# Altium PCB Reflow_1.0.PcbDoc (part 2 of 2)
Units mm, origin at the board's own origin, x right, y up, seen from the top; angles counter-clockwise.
Board outline 183 x 128.5 mm, 2 copper layers (Top Layer, Bottom Layer); 137 components, 94 nets, 418 pads, 91 vias.
Unrouted connection lines stored in the file: 2.
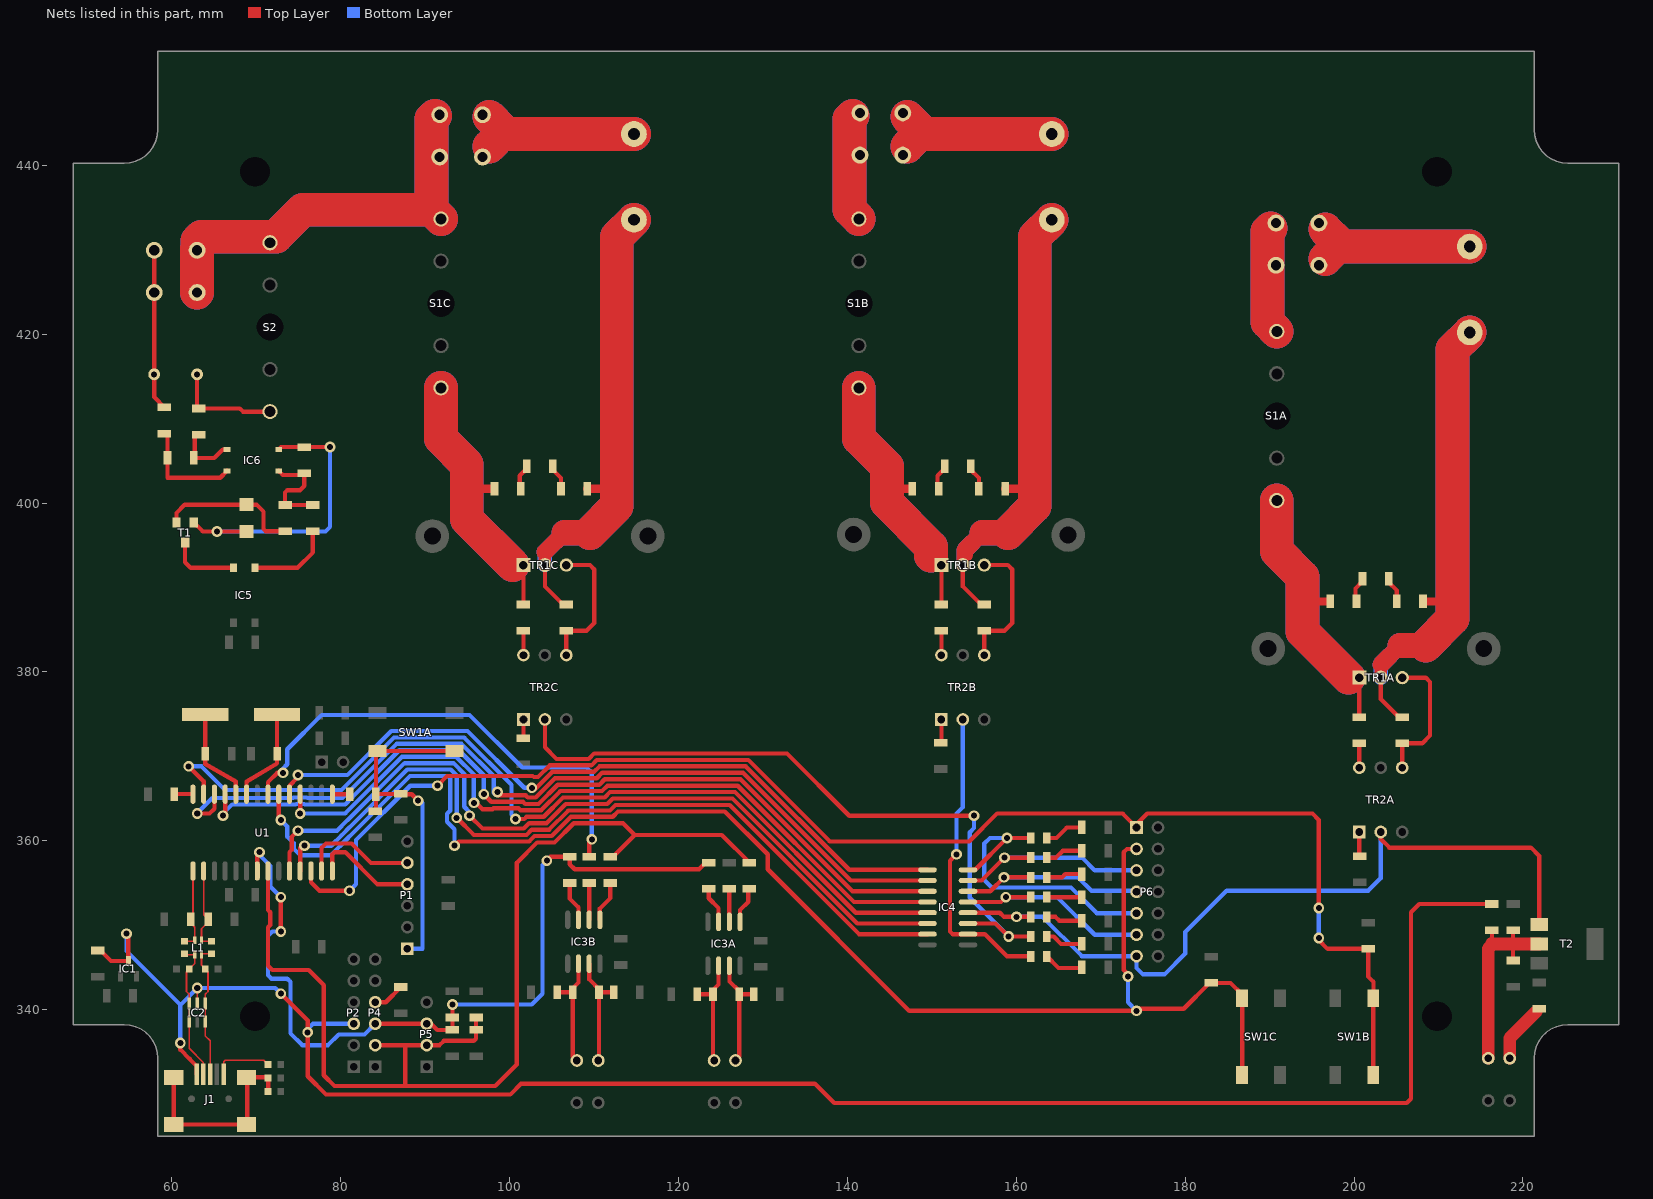
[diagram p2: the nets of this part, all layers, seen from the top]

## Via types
v1: diameter 1.27, hole 0.711, Top Layer to Bottom Layer, 91 vias

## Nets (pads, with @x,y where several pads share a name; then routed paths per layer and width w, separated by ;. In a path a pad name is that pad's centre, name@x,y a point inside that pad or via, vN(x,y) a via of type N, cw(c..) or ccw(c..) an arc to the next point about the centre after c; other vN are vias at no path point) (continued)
L1: K1.1 K4.1 K6.1 K7.1 S1A.1 S1B.1 S1C.1 S2.1 | length 147.7
  Top Layer w0.508: S2.1@71.12,431.292 71.143,431.292 S2.1@71.397,431.546
  Top Layer w4: K1.1@62.973,424.93 K1.1@62.973,429.93 62.992,431.038 63.5,431.546 S2.1@71.12,431.546 ; S2.1@71.397,431.546 72.329,431.546 75.529,434.746 90.745,434.746 ; K4.1@91.136,445.867 90.745,445.476 90.745,434.746 ; S1C.1@91.851,433.64 90.745,434.746 ; K6.1@140.636,445.867 140.245,445.476 140.245,434.746 S1B.1@141.351,433.64 ; K7.1@190.136,432.534 189.745,432.143 189.745,421.413 S1A.1@190.851,420.307
  Bottom Layer w4: K1.1@62.973,424.93 K1.1@62.973,429.93 62.992,431.038 63.5,431.546 S2.1@71.12,431.546 ; S2.1@71.397,431.546 72.329,431.546 75.529,434.746 90.745,434.746 ; K4.1@91.136,445.867 90.745,445.476 90.745,434.746 ; S1C.1@91.851,433.64 90.745,434.746 ; K6.1@140.636,445.867 140.245,445.476 140.245,434.746 S1B.1@141.351,433.64 ; K7.1@190.136,432.534 189.745,432.143 189.745,421.413 S1A.1@190.851,420.307
L_SICHER: C4.1 R33.1 S2.4 | length 12.7
  Top Layer w0.508: C4.1@62.973,415.238 62.973,411.402 R33.1@63.175,411.2 68.027,411.2 68.401,410.826 S2.4@71.609,410.826
MCLR: P1.1 R13.1 R14.2 R15A.1 SW1A.1 SW1A.2 | length 41.5
  Top Layer w0.5: R15A.1@84.074,363.5 84.156,363.582 R14.2@84.156,365.528 ; v1(89.154,364.744) 88.392,365.506 87.178,365.506 R13.1@87.106,365.578 87.056,365.528 R14.2@84.156,365.528 ; SW1A.2@93.45,370.622 SW1A.1@84.35,370.622 84.156,370.428 R14.2@84.156,365.528
  Bottom Layer w0.5: P1.1@87.884,347.218 89.662,347.218 89.662,364.49 v1@89.154,364.998
N: C4.2 K3.1 R35.1 | length 19.1
  Top Layer w0.508: K3.1@57.893,429.93 K3.1@57.893,424.93 C4.2@57.893,415.238 57.893,412.545 R35.1@59.111,411.327
Net*1A_0: *1A.0 R4A.2 R5A.2 TR1A.2 | length 113.1
  Top Layer w0.508: TR1A.2@203.17,379.319 203.17,376.779 205.303,374.646 R5A.2@205.71,374.646
  Top Layer w1: R4A.2@208.175,388.336 211.679,388.336
  Top Layer w1.5: TR1A.2@203.17,379.319 203.17,380.843
  Top Layer w2: 203.17,380.843 205.456,383.129
  Top Layer w3: 205.456,383.129 208.504,383.129
  Top Layer w4: 208.504,383.129 211.679,386.304 211.679,388.336 211.679,418.181 *1A.0@213.711,420.213
  Bottom Layer w1.5: TR1A.2@203.17,379.319 203.17,380.843
  Bottom Layer w1.7: TR1A.2@203.17,379.319 203.17,380.843 TR1A.2@203.17,379.319
  Bottom Layer w2: 203.17,380.843 205.456,383.129 ; 203.17,380.843 205.456,383.129 ; 203.17,380.843 205.456,383.129
  Bottom Layer w3: 205.456,383.129 208.504,383.129
  Bottom Layer w4: 208.504,383.129 211.679,386.304 211.679,388.336 211.679,418.181 *1A.0@213.711,420.213
Net*1A_1: *1A.1 K8.1 | length 40.8
  Top Layer w4: 196.583,428.901 198.055,430.373 ; 196.583,432.417 198.055,430.945 198.055,430.373 ; *1A.1@213.711,430.373 198.055,430.373
  Bottom Layer w4: 196.583,428.901 198.055,430.373 ; 196.583,432.417 198.055,430.945 198.055,430.373 ; *1A.1@213.711,430.373 198.055,430.373
Net*1B_0: *1B.0 R4B.2 R5B.2 TR1B.2 | length 103.6
  Top Layer w0.508: TR1B.2@153.67,392.652 153.67,390.112 155.803,387.979 R5B.2@156.21,387.979
  Top Layer w1: R4B.2@158.675,401.669 162.179,401.669
  Top Layer w1.5: TR1B.2@153.67,392.652 153.67,393.675 153.899,393.903
  Top Layer w2: 153.899,393.903 153.899,394.405 155.956,396.462
  Top Layer w3: 155.956,396.462 159.004,396.462
  Top Layer w4: 159.004,396.462 162.179,399.637 162.179,401.669 162.179,431.514 *1B.0@164.211,433.546
  Bottom Layer w1.5: TR1B.2@153.67,392.652 153.67,393.878 153.899,394.106
  Bottom Layer w2: 153.899,394.106 153.899,394.405 155.956,396.462
  Bottom Layer w3: 155.956,396.462 159.004,396.462
  Bottom Layer w4: 159.004,396.462 162.179,399.637 162.179,431.514 *1B.0@164.211,433.546
Net*1B_1: *1B.1 K2.1 | length 40.8
  Top Layer w4: 147.083,442.234 148.555,443.706 ; K2.1@147.083,445.75 148.555,444.278 148.555,443.706 ; *1B.1@164.211,443.706 148.555,443.706
  Bottom Layer w4: 147.083,442.234 148.555,443.706 ; K2.1@147.083,445.75 148.555,444.278 148.555,443.706 ; *1B.1@164.211,443.706 148.555,443.706
Net*1C_0: *1C.0 R4C.2 R5C.2 TR1C.2 | length 113.1
  Top Layer w0.508: TR1C.2@104.17,392.652 104.17,390.112 106.303,387.979 R5C.2@106.71,387.979
  Top Layer w1: R4C.2@109.175,401.669 112.679,401.669
  Top Layer w1.5: TR1C.2@104.17,392.652 104.17,394.176
  Top Layer w2: 104.17,394.176 106.456,396.462
  Top Layer w3: 106.456,396.462 109.504,396.462
  Top Layer w4: 109.504,396.462 112.679,399.637 112.679,401.669 112.679,431.514 *1C.0@114.711,433.546
  Bottom Layer w1.5: TR1C.2@104.17,392.652 104.17,394.176
  Bottom Layer w1.7: TR1C.2@104.17,392.652 104.17,394.176 TR1C.2@104.17,392.652
  Bottom Layer w2: 104.17,394.176 106.456,396.462 ; 104.17,394.176 106.456,396.462 ; 104.17,394.176 106.456,396.462
  Bottom Layer w3: 106.456,396.462 109.504,396.462
  Bottom Layer w4: 109.504,396.462 112.679,399.637 112.679,401.669 112.679,431.514 *1C.0@114.711,433.546
Net*1C_1: *1C.1 K5.1 | length 40.8
  Top Layer w4: 97.583,442.234 99.055,443.706 ; K5.1@97.583,445.75 99.055,444.278 99.055,443.706 ; *1C.1@114.711,443.706 99.055,443.706
  Bottom Layer w4: 97.583,442.234 99.055,443.706 ; K5.1@97.583,445.75 99.055,444.278 99.055,443.706 ; *1C.1@114.711,443.706 99.055,443.706
NetC3A_1: C3A.1 R3A.2 | length 3
  Top Layer w0.508: R3A.2@200.174,388.336 200.174,389.886 201.011,390.723 C3A.1@201.011,391.003
NetC3A_2: C3A.2 R4A.1 | length 3.1
  Top Layer w0.508: C3A.2@204.111,391.003 204.111,390.596 205.075,389.632 R4A.1@205.075,388.336
NetC3B_1: C3B.1 R3B.2 | length 3
  Top Layer w0.508: R3B.2@150.674,401.669 150.674,403.219 151.511,404.056 C3B.1@151.511,404.336
NetC3B_2: C3B.2 R4B.1 | length 3.1
  Top Layer w0.508: C3B.2@154.611,404.336 154.611,403.929 155.575,402.965 R4B.1@155.575,401.669
NetC3C_1: C3C.1 R3C.2 | length 3
  Top Layer w0.508: R3C.2@101.174,401.669 101.174,403.219 102.011,404.056 C3C.1@102.011,404.336
NetC3C_2: C3C.2 R4C.1 | length 3.1
  Top Layer w0.508: C3C.2@105.111,404.336 105.111,403.929 106.075,402.965 R4C.1@106.075,401.669
NetC7_1: C7.1 FER1.2 J1.6 J1.7 J1.8 J1.9 | length 24
  Top Layer w0.508: J1.8@60.198,331.978 J1.9@60.198,326.39 J1.6@68.834,326.39 68.917,326.473 J1.7@68.917,331.978 ; J1.7@68.834,331.978 J1.7@68.917,331.978 ; FER1.2@71.386,330.295 C7.1@71.386,331.895 71.303,331.978 J1.7@68.917,331.978
NetC9A_1: C9A.1 IC3A.3 K12.1 R12A.2 | length 13.6
  Top Layer w0.508: IC3A.3@126.011,345.199 126.037,345.173 126.037,343.328 127.18,342.185 C9A.1@127.18,341.83 ; K12.1@126.746,333.97 127.18,334.404 C9A.1@127.18,341.83 ; R12A.2@128.906,341.83 C9A.1@127.18,341.83
NetC9A_2: C9A.2 IC3A.2 K11.1 R11A.2 | length 13.4
  Top Layer w0.508: R11A.2@122.227,341.83 C9A.2@124.08,341.83 ; K11.1@124.206,333.97 124.08,334.096 C9A.2@124.08,341.83 ; IC3A.2@124.741,345.199 124.741,342.973 124.08,342.312 C9A.2@124.08,341.83
NetC9B_1: C9B.1 IC3B.3 K10.1 R12B.2 | length 13.7
  Top Layer w0.508: IC3B.3@109.411,345.434 109.437,345.408 109.437,343.563 110.58,342.42 C9B.1@110.58,342.065 ; K10.1@110.49,333.97 110.58,334.06 C9B.1@110.58,342.065 ; R12B.2@112.306,342.065 C9B.1@110.58,342.065
NetC9B_2: C9B.2 IC3B.2 K9.1 R11B.2 | length 13.8
  Top Layer w0.508: R11B.2@105.627,342.065 C9B.2@107.48,342.065 ; K9.1@107.95,333.97 107.48,334.44 C9B.2@107.48,342.065 ; IC3B.2@108.141,345.434 108.141,343.208 107.48,342.547 C9B.2@107.48,342.065
NetC10_1: C10.1 U1.14 | length 2.2
  Top Layer w0.508: C10.1@60.256,365.528 U1.14@62.484,365.515
NetC14_1: C14.1 IC6.1 R32.2 R34.2 | length 12.2
  Top Layer w0.508: IC6.1@72.632,403.808 73.133,403.307 75.452,403.307 R34.2@75.673,403.528 75.673,402.03 75.165,401.522 73.667,401.522 73.387,401.242 C14.1@73.387,399.77 ; C14.1@73.413,399.77 R32.2@76.689,399.77
NetC14_2: C14.2 D1.A T1.E | length 16.9
  Top Layer w0.508: T1.E@60.534,397.712 60.534,398.829 61.512,399.808 D1.A@68.815,399.808 70.021,399.808 70.847,398.982 70.847,396.924 71.101,396.67 C14.2@73.387,396.67
NetC15_1: C15.1 IC6.3 R33.2 | length 7
  Top Layer w0.508: C15.1@62.566,405.332 65.005,405.332 66.021,406.348 IC6.3@66.522,406.348 ; C15.1@62.695,405.461 R33.2@62.695,408.131
NetC15_2: C15.2 IC6.4 R35.2 | length 12.8
  Top Layer w0.508: R35.2@59.111,408.227 59.466,407.872 C15.2@59.466,405.332 59.466,402.997 65.711,402.997 IC6.4@66.522,403.808
NetD1_K: D1.K IC6.2 R34.1 T1.B | length 36
  Top Layer w0.508: T1.B@62.566,397.712 63.657,396.621 65.311,396.621 v1(65.322,396.633) D1.K@68.815,396.633 ; IC6.2@72.632,406.348 72.912,406.628 R34.1@75.673,406.628 v1(78.721,406.628)
  Bottom Layer w0.508: v1(65.322,396.633) 78.175,396.633 78.721,397.178 v1(78.721,406.628)
NetFER2_1: FER2.1 J1.1 | length 7
  Top Layer w0.2: J1.1@66.117,332.338 66.117,333.833 66.294,334.01 70.878,334.01 FER2.1@71.386,333.502
NetIC3A_5: IC3A.5 R29.2 | length 4.4
  Top Layer w0.508: IC3A.5@127.281,350.399 127.281,351.79 128.27,352.779 128.27,354.175 R29.2@128.399,354.304
NetIC3A_6: IC3A.6 R28.2 | length 3.9
  Top Layer w0.508: IC3A.6@126.011,350.399 R28.2@126.011,354.304
NetIC3A_7: IC3A.7 R30.2 | length 4.4
  Top Layer w0.508: R30.2@123.573,354.304 123.573,353.185 124.741,352.017 IC3A.7@124.741,350.399
NetIC3B_5: IC3B.5 R24.2 | length 4.9
  Top Layer w0.508: IC3B.5@110.681,350.634 110.681,351.981 111.925,353.225 R24.2@111.925,354.993
NetIC3B_6: IC3B.6 R23.2 | length 4.4
  Top Layer w0.508: IC3B.6@109.411,350.634 109.411,354.967 R23.2@109.437,354.993
NetIC3B_7: IC3B.7 R25.2 | length 4.8
  Top Layer w0.508: R25.2@107.099,354.993 107.099,353.149 108.141,352.107 IC3B.7@108.141,350.634
NetIC4_1: IC4.1 U1.5 | length 88.5
  Top Layer w0.508: U1.5@73.914,365.515 73.914,366.522 74.93,367.538 v1(74.93,367.792) ; v1(102.616,366.268) 102.87,366.014 102.901,366.014 105.052,368.165 109.985,368.165 110.628,368.808 127.954,368.808 140.207,356.555 IC4.1@149.48,356.555
  Bottom Layer w0.508: v1(74.93,367.792) 80.772,367.792 85.979,372.999 95,372.999 101.731,366.268 v1(102.616,366.268)
NetIC4_2: IC4.2 U1.12 | length 105.1
  Top Layer w0.508: v1(62.992,363.22) 64.454,363.22 65.024,363.79 U1.12@65.024,365.515 ; v1(98.552,365.76) 98.298,365.76 98.679,365.379 101.889,365.379 102.143,365.125 103.089,365.125 105.368,367.403 110.301,367.403 110.944,368.046 127.639,368.046 140.4,355.285 IC4.2@149.48,355.285
  Bottom Layer w0.508: v1(62.992,363.22) 62.992,363.282 64.774,365.063 74.333,365.063 74.395,365.125 75.973,365.125 76.035,365.063 80.199,365.063 81.149,366.014 86.61,371.475 94.288,371.475 98.109,367.654 98.109,365.695 98.298,365.506 98.298,365.76 v1(98.552,365.76)
NetIC4_3: IC4.3 U1.11 | length 100.5
  Top Layer w0.508: v1@65.786,362.712 66.294,363.22 U1.11@66.294,365.515 ; v1(96.936,365.506) 97.825,364.617 101.573,364.617 101.827,364.363 103.405,364.363 105.683,366.641 110.617,366.641 111.259,367.284 127.323,367.284 140.592,354.015 IC4.3@149.48,354.015
  Bottom Layer w0.508: v1(66.04,362.966) 66.04,363.22 67.121,364.301 74.649,364.301 74.711,364.363 75.657,364.363 75.719,364.301 80.514,364.301 81.338,365.125 86.926,370.713 93.973,370.713 96.936,367.75 v1(96.936,365.506)
NetIC4_4: IC4.4 U1.4 | length 91
  Top Layer w0.508: v1(75.184,363.22) U1.4@75.184,365.515 ; v1(95.758,364.49) 96.012,364.49 96.774,363.728 97.952,363.728 98.079,363.855 101.034,363.855 101.288,363.601 103.721,363.601 105.999,365.879 110.932,365.879 111.575,366.522 127.007,366.522 140.784,352.745 IC4.4@149.48,352.745
  Bottom Layer w0.508: v1(75.184,363.22) 80.511,363.22 87.242,369.951 93.657,369.951 95.758,367.85 v1(95.758,364.49)
NetIC4_5: IC4.5 U1.13 | length 108.6
  Top Layer w0.508: v1(61.976,368.808) 63.754,367.03 U1.13@63.754,365.515 ; v1(100.688,362.585) 101.734,362.585 101.988,362.839 104.036,362.839 106.314,365.117 111.248,365.117 111.891,365.76 126.692,365.76 140.977,351.475 IC4.5@149.48,351.475
  Bottom Layer w0.508: v1(61.976,368.808) 63.5,368.808 66.294,366.014 80.072,366.014 86.295,372.237 94.604,372.237 100.203,366.638 100.203,363.07 v1(100.688,362.585)
NetIC4_6: IC4.6 U1.24 | length 96.6
  Top Layer w0.508: U1.24@73.914,356.415 73.914,358.648 74.168,358.902 74.168,360.426 v1(74.93,361.188) ; v1@95.25,363.22 v1(95.25,362.966) 96.774,361.442 101.669,361.442 102.304,362.077 104.352,362.077 106.63,364.355 111.563,364.355 112.206,364.998 126.376,364.998 141.169,350.205 IC4.6@149.48,350.205
  Bottom Layer w0.508: v1(74.93,361.188) 79.544,361.188 80.746,362.39 80.758,362.39 87.557,369.189 93.341,369.189 94.615,367.915 94.615,364.017 95.25,363.382 v1(95.25,362.966)
NetIC4_7: IC4.7 U1.25 | length 95.2
  Top Layer w0.508: U1.25@75.184,356.415 75.184,359.156 75.438,359.41 v1(75.692,359.41) ; v1(93.726,362.712) 95.758,360.68 101.985,360.68 102.62,361.315 104.668,361.315 106.946,363.593 111.879,363.593 112.522,364.236 126.061,364.236 141.362,348.935 IC4.7@149.48,348.935
  Bottom Layer w0.508: v1(75.692,359.41) 78.856,359.41 80.123,360.678 80.123,360.69 81.062,361.628 81.074,361.628 87.873,368.427 93.026,368.427 93.726,367.727 v1(93.726,362.712) v1@93.98,362.966
NetIC5_A: IC5.A R32.1 | length 10.1
  Top Layer w0.508: IC5.A@69.831,392.326 74.859,392.326 76.689,394.156 R32.1@76.689,396.67
NetIC5_KA: IC5.KA T1.C | length 8.3
  Top Layer w0.508: T1.C@61.55,395.299 61.55,392.987 62.211,392.326 IC5.KA@67.291,392.326
NetK13_1: K13.1 R36.2 R37.2 R38.2 T2.2 | length 24.6
  Top Layer w0.508: 216.342,347.66 R36.2@216.342,349.412 ; R38.2@218.842,345.812 218.842,347.776 R37.2@218.842,349.412
  Top Layer w1.5: K13.1@215.9,334.224 215.9,347.218 216.342,347.66 ; 216.342,347.876 216.442,347.776 218.842,347.776 T2.2@221.942,347.776
NetK14_1: K14.1 R39.1 | length 6.8
  Top Layer w1.5: K14.1@218.44,334.224 218.44,336.61 R39.1@221.585,339.755
NetOPTO1A_A: OPTO1A.A R10A.1 | length 4.8
  Top Layer w0.508: OPTO1A.A@163.614,346.31 164.992,344.932 167.687,344.932 R10A.1@167.772,345.017
NetOPTO1B_A: OPTO1B.A R10B.1 | length 4.5
  Top Layer w0.508: OPTO1B.A@163.614,348.647 164.433,348.647 165.304,347.776 R10B.1@167.772,347.776
NetOPTO1C_A: OPTO1C.A R10C.1 | length 4.3
  Top Layer w0.508: OPTO1C.A@163.614,350.985 164.635,350.985 165.086,350.534 R10C.1@167.772,350.534
NetOPTO1D_A: OPTO1D.A R10D.1 | length 4.2
  Top Layer w0.508: OPTO1D.A@163.614,353.322 167.743,353.322 R10D.1@167.772,353.293
NetOPTO1E_A: OPTO1E.A R10E.1 | length 4.7
  Top Layer w0.508: OPTO1E.A@163.614,360.334 164.754,360.334 165.989,361.569 R10E.1@167.772,361.569
NetOPTO1F_A: OPTO1F.A R10F.1 | length 4.3
  Top Layer w0.508: OPTO1F.A@163.614,355.659 165.413,355.659 165.806,356.052 R10F.1@167.772,356.052
NetOPTO1G_A: OPTO1G.A R10G.1 | length 4.5
  Top Layer w0.508: OPTO1G.A@163.614,357.997 164.703,357.997 165.516,358.81 R10G.1@167.772,358.81
NetP4_2: P4.2 P5.2 R21.2 R24.1 R27.1 R29.1 U1.22 | length 133.3
  Top Layer w0.508: U1.22@71.374,356.415 71.374,351.79 71.628,351.536 71.628,350.012 71.374,349.758 71.374,345.186 71.882,344.678 76.2,344.678 77.978,342.9 77.978,332.232 79.248,330.962 87.63,330.962 ; P4.2@84.074,335.788 87.63,335.788 ; R27.1@96.012,339.064 R21.2@96.012,337.592 96.012,336.55 95.758,336.296 92.202,336.296 91.694,335.788 P5.2@90.17,335.788 87.63,335.788 ; R24.1@111.553,358.093 112.221,358.093 114.808,360.68 ; R29.1@128.399,357.404 125.123,360.68 114.808,360.68 ; 87.63,330.962 87.63,335.788 ; 87.63,330.962 98.298,330.962 100.838,333.502 100.838,357.378 103.251,359.791 105.299,359.791 107.577,362.069 113.419,362.069 114.808,360.68
NetP4_3: P4.3 P5.3 R22.2 R25.1 R26.1 R30.1 U1.21 | length 101
  Top Layer w0.508: U1.21@70.104,356.415 70.104,358.394 v1(70.358,358.648) ; v1(72.898,349.25) v1(72.898,353.314) ; P4.3@84.074,338.328 P5.3@90.17,338.328 90.678,338.328 91.414,337.592 R22.2@93.218,337.592 R26.1@93.218,339.064 v1(93.218,340.614) ; v1(104.394,357.632) 104.394,357.65 104.837,358.093 R25.1@107.099,358.093 107.099,357.213 107.696,356.616 122.428,356.616 123.216,357.404 R30.1@123.573,357.404
  Bottom Layer w0.508: v1@69.977,358.648 v1@70.019,358.648 ; v1@69.977,358.649 70.018,358.649 v1@70.019,358.648 ; v1(70.358,358.648) v1@70.019,358.648 ; v1(72.898,349.25) 71.882,349.25 71.374,348.742 71.374,344.083 71.795,343.662 73.66,343.662 74.041,343.281 74.041,337.185 75.438,335.788 78.486,335.788 79.756,337.058 82.804,337.058 P4.3@84.074,338.328 ; v1(72.898,353.314) 71.67,354.542 71.67,356.997 v1@70.019,358.648 ; v1(93.218,340.614) 102.616,340.614 103.886,341.884 103.886,357.124 v1(104.394,357.632)
NetP4_4: P4.4 R20.1 | length 3.8
  Top Layer w0.508: P4.4@84.074,340.868 85.318,340.868 R20.1@87.122,342.672
NetP6_1: P6.1 R15B.1 SW1B.1 SW1B.2 U1.26 | length 174.8
  Top Layer w0.508: U1.26@76.454,356.415 76.454,355.092 77.47,354.076 v1(81.026,354.076) ; v1(91.44,366.522) 92.583,367.665 102.706,367.665 ; 102.87,367.538 103.347,367.538 104.736,368.927 109.67,368.927 110.313,369.57 128.27,369.57 137.922,359.918 154.432,359.918 157.734,363.22 172.593,363.22 P6.1@174.244,361.569 174.244,361.95 175.514,363.22 195.072,363.22 195.834,362.458 195.834,356.616 ; v1(195.834,348.488) 195.834,348.234 196.876,347.192 R15B.1@201.676,347.192 201.676,343.916 202.311,343.281 SW1B.2@202.311,341.071 ; v1(195.834,352.044) 195.834,356.616 ; 195.834,355.854 195.834,356.616 ; SW1B.1@202.275,332.254 SW1B.2@202.275,341.354 SW1B.2@202.275,341.666
  Bottom Layer w0.508: v1(81.026,354.076) 81.788,354.838 81.788,360.089 88.221,366.522 v1(91.44,366.522) ; v1(195.834,348.488) v1(195.834,352.044)
NetP6_2: P6.2 R15C.1 SW1C.1 SW1C.2 U1.6 | length 176.5
  Top Layer w0.508: U1.6@72.644,365.515 72.644,362.712 v1(72.898,362.458) ; v1(93.472,359.41) 93.98,359.918 102.3,359.918 102.935,360.553 104.983,360.553 107.261,362.831 107.893,362.831 112.195,362.831 112.838,363.474 125.476,363.474 130.556,358.394 130.556,356.616 147.32,339.852 v1(174.244,339.852) 174.498,340.106 179.832,340.106 182.886,343.16 R15C.1@183.092,343.16 185.363,343.16 SW1C.1@186.715,341.808 ; v1(173.228,343.916) 173.228,344.17 172.72,344.678 172.72,358.648 173.101,359.029 P6.2@174.244,359.029 ; SW1C.2@186.766,332.378 SW1C.1@186.766,341.478
  Bottom Layer w0.508: v1(72.898,362.458) 73.66,361.696 73.66,360.488 74.407,359.741 74.407,359.079 75.219,358.267 78.79,358.267 80.885,360.362 80.885,360.374 81.377,360.866 81.389,360.866 88.188,367.665 92.71,367.665 92.964,367.411 92.964,363.566 92.583,363.185 92.583,362.239 93.472,361.35 v1(93.472,359.41) ; v1(173.228,343.916) 173.228,340.868 v1(174.244,339.852)
NetR1A_2: R1A.2 TR2A.1 | length 2.9
  Top Layer w0.508: TR2A.1@200.63,361.031 200.63,358.196 R1A.2@200.66,358.166
NetR1B_2: R1B.2 TR2B.1 | length 2.8
  Top Layer w0.5: R1B.2@151.069,371.596 151.13,371.657 TR2B.1@151.13,374.364
NetR1C_2: R1C.2 TR2C.1 | length 2.3
  Top Layer w0.5: R1C.2@101.63,372.11 TR2C.1@101.63,374.364
NetR2A_1: R2A.1 R3A.1 S1A.4 TR1A.1 | length 61.7
  Top Layer w0.508: R2A.1@200.63,374.646 TR1A.1@200.63,379.319
  Top Layer w1: 193.899,388.336 R3A.1@196.947,388.336 ; 199.36,379.319 TR1A.1@200.63,379.319
  Top Layer w4: S1A.4@190.851,400.307 190.851,394.305 193.899,391.257 193.899,384.78 199.36,379.319
  Bottom Layer w1: 198.217,379.319 TR1A.1@200.63,379.319 199.36,379.319
  Bottom Layer w4: S1A.4@190.851,400.307 190.851,394.305 193.899,391.257 193.899,384.78 199.36,379.319
NetR2A_2: R2A.2 TR2A.6 | length 2.9
  Top Layer w0.508: TR2A.6@200.63,368.651 R2A.2@200.63,371.546
NetR2B_1: R2B.1 R3B.1 S1B.4 TR1B.1 | length 59.4
  Top Layer w0.508: R2B.1@151.13,387.979 TR1B.1@151.13,392.652
  Top Layer w1: 144.399,401.669 144.678,401.669 R3B.1@147.447,401.669 ; 150.07,392.652 TR1B.1@151.13,392.652
  Top Layer w4: S1B.4@141.351,413.64 141.351,407.638 144.678,404.311 144.678,401.669 144.678,400.05 149.911,394.818 149.911,393.776
  Bottom Layer w1: 144.399,401.669 144.678,401.669 ; 150.07,392.652 TR1B.1@151.13,392.652 ; TR1B.1@151.13,392.652 149.892,392.652 TR1B.1@151.13,392.652
  Bottom Layer w4: S1B.4@141.351,413.64 141.351,407.638 144.678,404.311 144.678,401.669 144.678,400.05 149.911,394.818 149.911,393.776
NetR2B_2: R2B.2 TR2B.6 | length 2.9
  Top Layer w0.508: TR2B.6@151.13,381.984 R2B.2@151.13,384.879
NetR2C_1: R2C.1 R3C.1 S1C.4 TR1C.1 | length 61.7
  Top Layer w0.508: R2C.1@101.63,387.979 TR1C.1@101.63,392.652
  Top Layer w1: 94.899,401.669 R3C.1@97.947,401.669 ; 100.36,392.652 TR1C.1@101.63,392.652
  Top Layer w4: S1C.4@91.851,413.64 91.851,407.638 94.899,404.59 94.899,398.113 100.36,392.652
  Bottom Layer w1: 99.217,392.652 TR1C.1@101.63,392.652 100.36,392.652
  Bottom Layer w4: S1C.4@91.851,413.64 91.851,407.638 94.899,404.59 94.899,398.113 100.36,392.652
NetR2C_2: R2C.2 TR2C.6 | length 2.9
  Top Layer w0.508: TR2C.6@101.63,381.984 R2C.2@101.63,384.879
NetR5A_1: R5A.1 TR1A.3 TR2A.4 | length 16.4
  Top Layer w0.508: TR2A.4@205.71,368.651 R5A.1@205.71,371.546 208.097,371.546 209.012,372.461 209.012,378.811 208.504,379.319 TR1A.3@205.71,379.319
NetR5B_1: R5B.1 TR1B.3 TR2B.4 | length 16.4
  Top Layer w0.508: TR2B.4@156.21,381.984 R5B.1@156.21,384.879 158.597,384.879 159.512,385.794 159.512,392.144 159.004,392.652 TR1B.3@156.21,392.652
NetR5C_1: R5C.1 TR1C.3 TR2C.4 | length 16.4
  Top Layer w0.508: TR2C.4@106.71,381.984 R5C.1@106.71,384.879 109.097,384.879 110.012,385.794 110.012,392.144 109.504,392.652 TR1C.3@106.71,392.652
NetR23_1: R23.1 U1.7 | length 57.3
  Top Layer w0.508: U1.7@71.374,365.515 71.374,366.94 72.48,368.046 v1(73.152,368.046) ; R23.1@109.437,358.093 109.437,359.881 v1(109.728,360.172)
  Bottom Layer w0.508: v1(73.152,368.046) 73.152,368.554 73.66,369.062 73.66,370.84 77.724,374.904 95.25,374.904 101.49,368.664 109.11,368.664 109.728,368.046 v1(109.728,360.172)
OUT1: IC4.10 OPTO1A.K TR2B.2 | length 36.5
  Top Layer w0.508: v1(152.908,358.394) 152.146,357.632 152.146,349.25 152.461,348.935 IC4.10@154.28,348.935 156.271,348.935 158.896,346.31 OPTO1A.K@161.714,346.31
  Bottom Layer w0.508: v1(152.908,358.394) 152.908,363.22 153.67,363.982 TR2B.2@153.67,374.364
OUT2: IC4.11 OPTO1B.K TR2C.2 | length 82.5
  Top Layer w0.508: TR2C.2@104.17,374.364 104.17,371.064 105.545,369.689 109.354,369.689 109.997,370.332 132.842,370.332 140.208,362.966 v1(155,362.966) ; IC4.11@154.28,350.205 157.541,350.205 v1(159.099,348.647) OPTO1B.K@161.714,348.647
  Bottom Layer w0.508: v1(155,362.966) 155,361.5 154.5,361 154.5,353.246 v1(159.099,348.647)
OUT3: IC4.12 OPTO1C.K P6.7 T2.1 TR2A.2 | length 94.7
  Top Layer w0.508: IC4.12@154.28,351.475 158.049,351.475 158.539,350.985 v1(160.02,350.985) OPTO1C.K@161.714,350.985 ; TR2A.2@203.17,361.031 203.17,360.202 204.186,359.186 220.95,359.186 221.942,358.194 T2.1@221.942,350.062
  Bottom Layer w0.508: v1(160.02,350.985) 163.111,350.985 167.767,346.329 P6.7@174.244,346.329 174.244,344.932 175.006,344.17 177.546,344.17 180.022,346.647 180.022,349.186 184.912,354.076 201.676,354.076 203.17,355.57 TR2A.2@203.17,361.031
OUT4: IC4.13 OPTO1D.K P6.6 | length 25
  Top Layer w0.508: IC4.13@154.28,352.745 158.181,352.745 v1(158.758,353.322) OPTO1D.K@161.714,353.322
  Bottom Layer w0.508: v1(158.758,353.322) 164.838,353.322 169.291,348.869 P6.6@174.244,348.869
OUT5: IC4.16 OPTO1E.K P6.5 | length 36
  Top Layer w0.508: IC4.16@154.28,356.555 155.133,356.555 v1(158.912,360.334) OPTO1E.K@161.714,360.334
  Bottom Layer w0.508: v1(158.912,360.334) 156.88,360.334 156.21,359.664 156.21,355.346 157.091,354.465 166.489,354.465 169.545,351.409 P6.5@174.244,351.409
OUT6: IC4.14 OPTO1F.K P6.4 | length 24.5
  Top Layer w0.508: IC4.14@154.28,354.015 156.911,354.015 v1(158.555,355.659) OPTO1F.K@161.714,355.659
  Bottom Layer w0.508: v1(158.555,355.659) 167.327,355.659 168.91,354.076 174.117,354.076 P6.4@174.244,353.949
OUT7: IC4.15 OPTO1G.K P6.3 | length 24.8
  Top Layer w0.508: IC4.15@154.28,355.285 155.895,355.285 v1(158.607,357.997) OPTO1G.K@161.714,357.997
  Bottom Layer w0.508: v1(158.607,357.997) 167.783,357.997 169.291,356.489 P6.3@174.244,356.489
PGC: P1.5 U1.27 | length 14.1
  Top Layer w0.5: U1.27@77.724,356.415 77.724,359.156 78.232,359.664 81.28,359.664 83.566,357.378 P1.5@87.884,357.378
PGD: P1.4 U1.28 | length 12.6
  Top Layer w0.5: U1.28@78.994,356.415 78.994,358.394 79.248,358.648 80.518,358.648 84.328,354.838 P1.4@87.884,354.838
TO_MCLR: R14.1 U1.1 | length 2.1
  Top Layer w0.5: U1.1@78.994,365.515 81.043,365.515 R14.1@81.056,365.528
TO_OSC1: C13.2 U1.9 XTAL1.1 | length 11.5
  Top Layer w0.508: U1.9@68.834,365.515 68.834,367.028 72.441,369.163 C13.2@72.441,370.343 ; XTAL1.1@72.441,374.959 C13.2@72.441,370.343 ; C13.2@72.456,370.328 C13.2@72.441,370.343
TO_OSC2: C12.2 U1.10 XTAL1.2 | length 11.5
  Top Layer w0.508: XTAL1.2@63.941,374.959 63.941,370.343 C12.2@63.956,370.328 63.956,369.078 67.564,367.028 U1.10@67.564,365.515
USB1_N: C5.2 IC2.1 IC2.6 J1.4 L1.2 R8.1 | length 16.9
  Top Layer w0.2: R8.1@61.492,346.504 L1.2@62.692,346.504 62.692,345.466 C5.2@62.042,344.816 ; C5.2@62.042,344.49 C5.2@62.042,344.816 ; J1.4@63.717,332.338 63.717,333.738 62.042,335.412 IC2.1@62.042,338.579 IC2.6@62.042,340.729 62.042,341.818 61.722,342.138 61.722,344.496 C5.2@62.042,344.816
USB1_P: C6.2 IC2.3 IC2.4 J1.3 L1.3 R9.1 | length 16
  Top Layer w0.2: L1.3@63.492,346.504 63.492,345.266 C6.2@63.942,344.816 64.262,344.496 64.262,342.138 63.942,341.818 IC2.4@63.942,340.729 IC2.3@63.942,338.579 63.942,336.87 64.516,336.296 64.516,333.738 J1.3@64.517,332.338 ; L1.3@63.592,346.604 R9.1@64.692,346.604
USB_N: L1.1 R7.2 R8.2 U1.15 | length 9.6
  Top Layer w0.2: R8.2@61.492,348.104 L1.1@62.592,348.104 ; U1.15@62.484,356.415 62.484,350.967 R7.2@62.201,350.684 62.201,350.226 62.692,349.734 L1.1@62.692,348.204
USB_P: L1.4 R6.2 R9.2 U1.16 | length 9.4
  Top Layer w0.2: L1.4@63.492,348.204 63.492,349.575 64.051,350.134 R6.2@64.051,350.434 ; 63.692,348.104 R9.2@64.692,348.104 ; U1.16@63.754,356.415 63.754,351.23 R6.2@64.301,350.684
VBUS: C1.1 IC1.3 IC2.5 J1.5 P2.3 R36.1 | length 224.8
  Top Layer w0.2: IC2.5@62.992,340.729 v1(62.992,342.554)
  Top Layer w0.508: C1.1@51.23,347.002 51.53,347.002 52.78,345.752 IC1.3@54.83,345.752 54.83,348.522 v1@54.61,348.742 ; v1@61.101,335.945 v1(60.992,336.054) 60.992,335.255 62.083,334.164 62.09,334.164 62.917,333.338 J1.5@62.917,332.338 ; v1(72.898,341.884) 76.073,338.709 76.073,332.105 78.232,329.946 100.076,329.946 101.346,331.216 136.144,331.216 138.43,328.93 206.248,328.93 206.756,329.438 206.756,351.536 207.732,352.512 R36.1@216.342,352.512
  Bottom Layer w0.508: v1(54.61,348.996) 54.61,346.936 60.992,340.554 ; v1(60.992,336.054) 60.992,340.554 ; v1(72.898,341.884) 72.228,342.554 v1(62.992,342.554) 60.992,340.554 ; v1(76.073,337.312) 76.073,337.693 76.708,338.328 P2.3@81.534,338.328
pads on no net: IC3A.8 IC3B.8 J1. J1.2 K9.2 K10.2 K11.2 K12.2 K13.2 K14.2 P1.6 P2.2 P2.6 P5.4 S1A.2 S1A.3 S1A.5 S1B.2 S1B.3 S1B.5 S1C.2 S1C.3 S1C.5 S2.2 S2.3 S2.5 T2.4 TR2A.3 TR2A.5 TR2B.3 TR2B.5 TR2C.3 TR2C.5

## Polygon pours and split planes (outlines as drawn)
GND on Bottom Layer "Mechanical 2-No Net" (solid, remove dead copper, pour order 2): 58.09,335.6 57.795,336.232 57.395,336.803 56.902,337.296 56.331,337.696 55.699,337.991 55.026,338.171 54.331,338.232 48.5,338.232 48.5,387 88,387 99.5,375.5 186.5,375.5 199.5,362.5 231.331,362.5 231.331,338.232 225.331,338.232 224.636,338.171 223.963,337.991 223.331,337.696 222.76,337.296 222.267,336.803 221.867,336.232 221.572,335.6 221.392,334.927 221.331,334.232 221.331,324.982 58.331,324.982 58.331,334.232 58.27,334.927

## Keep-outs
Keep-Out Layer:
  the board outline again, w0.6

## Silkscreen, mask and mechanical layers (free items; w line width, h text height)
Top Overlay:
  drawing of 1479 lines, arcs and shapes, not listed
  text "Reflow-Controller V1.0" at 170.917,445.973 h5
  text "KD 2013" at 183.718,442.214 h3
  text "L1A in" at 87.706,440.131 h3 r90
  text "L1A out" at 101.879,440.131 h3 r90
  text "L1B in" at 137.617,440.131 h3 r90
  text "L1B out" at 151.79,440.131 h3 r90
  text "Nz" at 56.337,434.594 h3
  text "Lz" at 61.747,434.569 h3
  text "L1C in" at 187.02,427.203 h3 r90
  text "L1C out" at 201.193,427.203 h3 r90
  text "F2" at 85.827,422.504 h3 r90
  text "F3" at 135.433,422.377 h3 r90
  text "F1" at 79.654,419.049 h3 r90
  text "F4" at 184.861,409.118 h3 r90
  text "LEDs:" at 162.408,379.628 h3
  text "RESET" at 86.766,379.273 h3
  text "pin assignment" at 112.573,378.333 h3
  text "LED3" at 164.54,377.617 h2
  text "E" at 162.636,377.596 h2
  text "G" at 162.636,375.945 h2
  text "LED1" at 164.616,375.924 h2
  text "pin" at 112.725,375.564 h2
  text "P2" at 116.102,375.437 h2
  text "P4" at 125.653,375.437 h2
  text "P5" at 136.093,375.437 h2
  text "F" at 162.636,374.252 h2
  text "LED2" at 164.667,374.252 h2
  text "GND" at 116.102,372.949 h2
  text "GND" at 125.653,372.949 h2
  text "GND" at 136.093,372.949 h2
  text "1" at 113.588,372.928 h2
  text "D" at 162.636,372.58 h2
  text "LED4" at 164.616,372.58 h2
  text "N.C." at 116.102,371.095 h2
  text "SCK / SCL" at 125.653,371.095 h2
  text "SCK / SCL" at 136.093,371.095 h2
  text "2" at 113.398,371.074 h2
  text "C" at 162.636,370.929 h2
  text "Fan1 / External1" at 164.616,370.929 h2
  text "B" at 162.636,369.236 h2
  text "L1A (Heater1)" at 164.592,369.24 h2
  text "3" at 113.404,369.214 h2
  text "5V" at 116.102,369.214 h2
  text "SDI / SDA" at 125.653,369.192 h2
  text "SDI / SDA" at 136.093,369.192 h2
  text "A" at 162.636,367.563 h2
  text "L1B (Heater2)" at 164.592,367.563 h2
  text "4" at 113.379,367.36 h2
  text "FTDI TXD" at 116.102,367.36 h2
  text "SDO" at 125.653,367.337 h2
  text "5" at 113.399,365.375 h2
  text "CS (RC7) *" at 125.654,365.379 h2
  text "FTDI RXD" at 116.102,365.354 h2
  text "6" at 113.4,363.449 h2
  text "N.C." at 116.102,363.449 h2
  text "3V3" at 125.654,363.449 h2
  text "* requires R20" at 112.268,361.467 h1.52
  text "N.C." at 89.558,359.512 h1.52
  text "PGC" at 83.446,356.845 h1.52
  text "PWM / External" at 226.517,355.371 h3 r90
  text "PGD" at 83.464,354.279 h1.52
  text "GND" at 90.551,350.825 h1.52 r90
  text "3V3" at 83.933,349.301 h1.52
  text "MCLR" at 89.558,346.786 h1.52
  text "1" at 93.929,346.608 h2
  text "pin assignment for P6:" at 137.109,337.236 h3
  text "6 - LED4" at 146.71,334.232 h2
  text "1 - SW1B" at 137.262,334.213 h2
  text "T2-" at 117.805,333.959 h3
  text "T2+" at 129.159,333.959 h3
  text "1" at 78.867,332.537 h2
  text "2 - SW1C" at 137.26,332.537 h2
  text "7 - Fan1 / External1" at 146.71,332.539 h2
  text "1" at 86.004,332.435 h2
  text "1" at 87.706,332.435 h2
  text "3 - LED1" at 137.262,330.86 h2
  text "8 to 12 - GND" at 146.71,330.841 h2
  text "13 to 14 - +3.3V" at 146.71,329.209 h2
  text "4 - LED2" at 137.262,329.188 h2
  text "T1-" at 101.702,327.889 h3
  text "T1+" at 112.878,327.889 h3
  text "5 - LED3" at 137.262,327.533 h2
  text "START" at 183.845,327.279 h3
  text "SELECT" at 195.732,327.279 h3
  text "-" at 220.32,326.136 h2
  text "+" at 213.182,325.958 h2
